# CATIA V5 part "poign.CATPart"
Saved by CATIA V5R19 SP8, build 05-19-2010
Part number: poign
Bounding box of the stored display mesh (mm): x -32.375 to 32.375, y -32.277 to 32.277, z -32 to 42.41
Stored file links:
  G:\EU_thinkMotion\CFAO_2010\SIL_groupe1\SIL_groupe1\A reprendre\fbruguiere\fbruguiere\fbruguiere\poign.CATPart
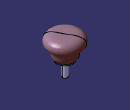
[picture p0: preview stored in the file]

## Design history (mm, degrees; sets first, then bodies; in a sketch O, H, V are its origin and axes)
Body1 (main body)
  Sketch1 on yz-plane, origin (0, 0, 0), H (0, 1, 0), V (0, 0, 1)
    spline S1 through (0, 0.4848) (-21.163, 9.978) (-25.679, 20.5153) (-30.8222, 25.1567) (-31.7003, 33.9378) (-20.4103, 41.8408) (0, 42.2171)
    axis line L1 (0, -28.7244) -> (0, 42.7018)
    point P1 (0, -28.7244)
    line L2 (0, 42.2171) -> (0, 0.4848)
    point P3 (0, 42.2171)
    point P4 (0, 0.4848)
    point P5 (0, 0.4848)
    point P6 (0, 42.2171)
    coincidence: P5 V, P6 V, P1 V, P6 P3, P5 P4
    vertical: L1 V, L2 V
  Shaft1: profile Sketch1, axis Sketch1.L1, angle 360
  Sketch2 on xy-plane, origin (0, 0, 0), H (1, 0, 0), V (0, 1, 0)
    circle A1 centre (0, 0) radius 16
    reference projected point E1 (0, 0) from edge
    distance A1 E1 = 16
  Pad1: profile Sketch2, direction (0, 0, -1), length 2
  Sketch3 on end face of Pad1, origin (0, 0, -2), H (1, 0, 0), V (0, -1, 0)
    circle A1 centre (0, 0) radius 5
    reference projected point E1 (0, 0) from edge
    distance A1 E1 = 5
  Pad2: profile Sketch3, direction (0, 0, -1), length 30
  Chamfer1: length 1, angle 45, on edge [face of Pad2 from Sketch3.A1 | end face of Pad2]
  Sketch4 on end face of Pad1, origin (0, 0, -2), H (1, 0, 0), V (0, -1, 0)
